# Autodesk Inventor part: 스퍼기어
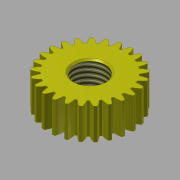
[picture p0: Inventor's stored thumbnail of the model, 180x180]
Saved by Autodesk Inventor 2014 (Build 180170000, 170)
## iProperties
Created: 2017-04
Part Number: 스퍼기어
Material: 강철
Document SubType Name: Modeling
Designer: mduedu
Categories: <?xml version="1.0" encoding="UTF-16"?> <MemberInstance><Categories><FamilyTemplate><FamilyTemplateParameter ValueType="xs:double" Id="1" ObjectReferenceKey="da
Density: 7.85 g/cm^3
Mass: 32.0047 g
Surface Area: 26.9526 cm^2
Volume: 4.07703 cm^3
Appearance: 노란색
CustomPartVersion: 1
Author: mduedu
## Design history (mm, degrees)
sketch "Sketch1"
  geometry: C1 r 13.5 at (0, 0)
  constraints: 1 centre point
  dimensions: "d0" = 27 diameter of C1 (= da_da)
extrude "Extrusion1" new body sketch "Sketch1" distance "d1" = 10 (= da_b); taper "d2" = 0 deg
workplane "Work Plane2"
sketch "Sketch2"
  geometry: C1 r 13.5 at (0, 0) reference; C2 r 12.5 at (0, 0)
  constraints: 1 centre point, 1 coincident
  dimensions: "d3" = 25 diameter of C2 (= da_dw)
feature "피치 지름" sketch "Sketch2" dims "d4" = 10, "d5" = 0
workplane "Work Plane8"
workplane "Work Plane9"
feature "스퍼 기어" dims "da_b" = 10, "da_d" = 25, "da_aw" = 25, "da_da" = 27, "da_df" = 22.5, "da_dw" = 25, angle "da_beta" = 0 deg, "da_lefttooth" = 0, "da_righttooth" = 0
sketch "스케치3"
  geometry: C1 r 5 at (0, 0); 1 further point
  constraints: 1 centre point, 1 coincident
  dimensions: "d49" = 10 diameter of C1
extrude "돌출2" cut sketch "스케치3" stored distance "d50" = 10; taper "d51" = 0 deg
feature "스레드1" dims "d52" = 10, "d53" = 0
chamfer "모따기1" distance "d54" = 0.5; stored, may be unused: second distance "d55" = 2, angle "d56" = 45 deg
body "Solid1"
body "Srf1"
other parameters: "d16" = 25 (= da_aw), "d17" = 0, "d34" = 1.25664 (computed from da_z), "d39" = 0, "d41" = 0, "d43" = 25 (= da_aw), "d46" = 25 (= da_aw), "d47" = 0, "d48" = 0
